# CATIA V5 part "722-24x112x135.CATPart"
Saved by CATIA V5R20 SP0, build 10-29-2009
Part number: 722-24x112x135
Definition: NONE
Nomenclature: 722-24x112x135
Source: Unknown
Description: 722-24x112x135
Bounding box of the stored display mesh (mm): x -12 to 12, y -11.818 to 11.818, z -100 to 35
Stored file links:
  C:\Users\Utente\Desktop\IO LAVORO\3D X SITO CF\X SITO\722\722-24x112x135.CATPart
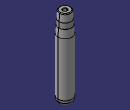
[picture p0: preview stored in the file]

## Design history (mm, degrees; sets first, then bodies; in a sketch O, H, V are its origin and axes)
Body1 "722-24x112x135" (main body)
  Solid1: solid without history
